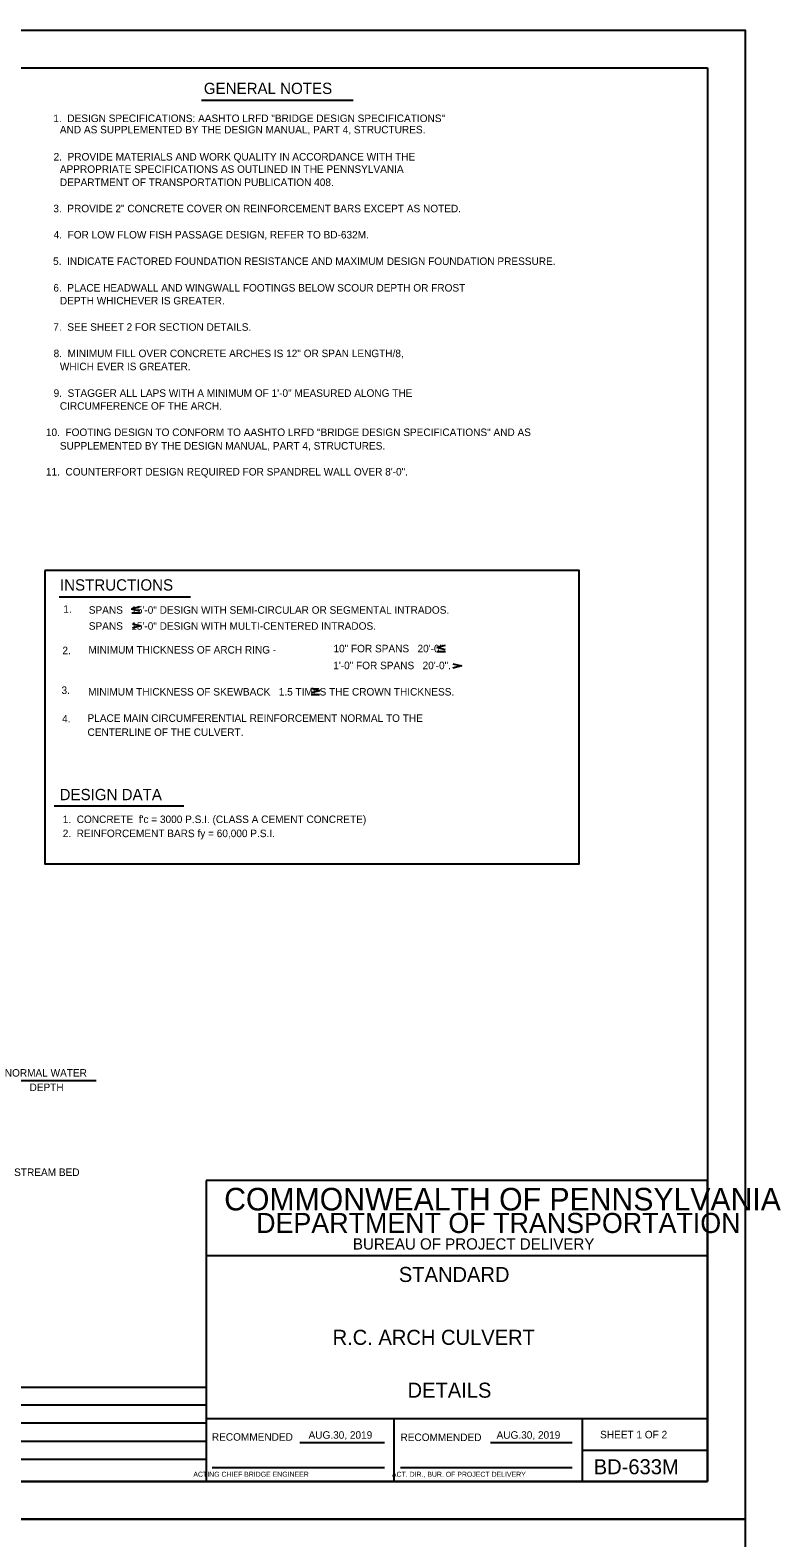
# Model space of a CAD drawing. Extents: x 639028 to 639883, y 298843 to 300031.
# Drawn here: x 639584 to 639883, y 299430 to 300031 of the extents above; entities that cross this region are included whole.
import ezdxf

# ---------------------------------------------------------------- set-up
doc = ezdxf.new("R2010")
doc.units = 0
for name, color, linetype in [('2', 7, 'Continuous'), ('53', 7, 'Continuous'), ('PLT-BNDY', 7, 'Continuous')]:
    doc.layers.add(name, color=color, linetype=linetype)

msp = doc.modelspace()

# ---------------------------------------------------------------- linework, layer by layer
at = {"layer": '2'}
for p, q in [((639067.74, 300016.08), (639853.74, 300016.08)), ((639853.74, 300016.08), (639853.74, 299452.08)), ((639627.38, 299800.99), (639624, 299800.11)), ((639627.38, 299799.24), (639624, 299800.11)), ((639627.52, 299798.42), (639624.14, 299798.42)), ((639749.17, 299785.64), (639745.8, 299784.76)), ((639749.17, 299783.89), (639745.8, 299784.76)), ((639749.31, 299783.07), (639745.94, 299783.07)), ((639695.65, 299765.98), (639699.02, 299765.98)), ((639695.78, 299768.55), (639699.16, 299767.67)), ((639695.78, 299766.8), (639699.16, 299767.67)), ((639571.61, 299612.08), (639609.99, 299612.08)), ((639853.74, 299572.08), (639653.74, 299572.08)), ((639653.74, 299572.08), (639653.74, 299452.08)), ((639853.74, 299452.08), (639853.74, 299572.08)), ((639853.74, 299542.08), (639653.74, 299542.08)), ((639446.74, 299489.7), (639653.74, 299489.7)), ((639446.74, 299482.58), (639653.74, 299482.58)), ((639653.74, 299482.58), (639653.74, 299452.08)), ((639446.74, 299475.45), (639653.74, 299475.45)), ((639853.74, 299477.08), (639653.74, 299477.08)), ((639728.74, 299452.08), (639728.74, 299477.08)), ((639803.74, 299477.08), (639803.74, 299452.08)), ((639446.74, 299468.2), (639653.74, 299468.2)), ((639691.2, 299467.58), (639724.89, 299467.58)), ((639767.18, 299467.58), (639799.79, 299467.58)), ((639803.74, 299464.58), (639853.74, 299464.58)), ((639446.74, 299460.95), (639653.74, 299460.95)), ((639656.24, 299457.58), (639724.89, 299457.58)), ((639731.36, 299457.58), (639799.79, 299457.58)), ((639853.74, 299452.08), (639067.74, 299452.08)), ((639446.74, 299452.08), (639653.74, 299452.08)), ((639653.74, 299452.08), (639853.74, 299452.08))]:
    msp.add_line(p, q, dxfattribs=at)
msp.add_lwpolyline([(639589.49, 299815.5), (639589.49, 299698.5), (639802.53, 299698.5), (639802.53, 299815.5)], close=True, dxfattribs=at)
for points in [[(639624.37, 299794.26), (639627.74, 299793.39), (639624.37, 299792.51)], [(639752.21, 299778.29), (639755.58, 299777.42), (639752.21, 299776.54)]]:
    msp.add_lwpolyline(points, dxfattribs=at)
at = {"layer": '53'}
for p, q in [((639652, 300003.17), (639712.38, 300003.17)), ((639595.24, 299805), (639647.61, 299805)), ((639593.24, 299721.66), (639644.86, 299721.66))]:
    msp.add_line(p, q, dxfattribs=at)
at = {"layer": 'PLT-BNDY'}
for points in [[(639027.74, 300031.08), (639868.74, 300031.08), (639868.74, 299437.08), (639027.74, 299437.08)], [(639027.74, 299437.08), (639868.74, 299437.08), (639868.74, 298843.08), (639027.74, 298843.08)]]:
    msp.add_lwpolyline(points, close=True, dxfattribs=at)

# ---------------------------------------------------------------- texts
at = {"layer": '2'}
for s, height, p in [('1.  DESIGN SPECIFICATIONS: AASHTO LRFD "BRIDGE DESIGN SPECIFICATIONS"', 3, (639592.86, 299994.41)), ('     AND AS SUPPLEMENTED BY THE DESIGN MANUAL, PART 4, STRUCTURES.', 3, (639589.89, 299989.9)), ('2.  PROVIDE MATERIALS AND WORK QUALITY IN ACCORDANCE WITH THE', 3, (639592.97, 299979.07)), ('     APPROPRIATE SPECIFICATIONS AS OUTLINED IN THE PENNSYLVANIA', 3, (639589.89, 299974.15)), ('     DEPARTMENT OF TRANSPORTATION PUBLICATION 408.', 3, (639589.89, 299968.9)), ('3.  PROVIDE 2" CONCRETE COVER ON REINFORCEMENT BARS EXCEPT AS NOTED.', 3, (639592.86, 299958.42)), ('4.  FOR LOW FLOW FISH PASSAGE DESIGN, REFER TO BD-632M.', 3, (639592.97, 299947.96)), ('5.  INDICATE FACTORED FOUNDATION RESISTANCE AND MAXIMUM DESIGN FOUNDATION PRESSURE.', 3, (639592.75, 299937.4)), ('6.  PLACE HEADWALL AND WINGWALL FOOTINGS BELOW SCOUR DEPTH OR FROST', 3, (639592.86, 299926.79)), ('     DEPTH WHICHEVER IS GREATER.', 3, (639589.89, 299921.65)), ('7.  SEE SHEET 2 FOR SECTION DETAILS.', 3, (639592.86, 299911.15)), ('8.  MINIMUM FILL OVER CONCRETE ARCHES IS 12" OR SPAN LENGTH/8,', 3, (639592.97, 299900.62)), ('     WHICH EVER IS GREATER.', 3, (639589.89, 299895.4)), ('9.  STAGGER ALL LAPS WITH A MINIMUM OF 1\'-0" MEASURED ALONG THE', 3, (639592.97, 299884.79)), ('     CIRCUMFERENCE OF THE ARCH.', 3, (639589.89, 299879.65)), ('10.  FOOTING DESIGN TO CONFORM TO AASHTO LRFD "BRIDGE DESIGN SPECIFICATIONS" AND AS', 3, (639589.89, 299869.15)), ('     SUPPLEMENTED BY THE DESIGN MANUAL, PART 4, STRUCTURES.', 3, (639589.89, 299863.75)), ('11.  COUNTERFORT DESIGN REQUIRED FOR SPANDREL WALL OVER 8\'-0".', 3, (639589.89, 299853.4)), ('1.', 3, (639596.86, 299798.62)), ('SPANS   15\'-0" DESIGN WITH SEMI-CIRCULAR OR SEGMENTAL INTRADOS.', 3, (639606.99, 299798.25)), ('SPANS   15\'-0" DESIGN WITH MULTI-CENTERED INTRADOS.', 3, (639606.99, 299791.87)), ('2.', 3, (639596.49, 299782.12)), ('MINIMUM THICKNESS OF ARCH RING -', 3, (639606.86, 299782.37)), ('10" FOR SPANS   20\'-0".', 3, (639704.56, 299782.87)), ('1\'-0" FOR SPANS   20\'-0".', 3, (639704.48, 299776.12)), ('3.', 3, (639596.11, 299766.25)), ('MINIMUM THICKNESS OF SKEWBACK   1.5 TIMES THE CROWN THICKNESS.', 3, (639606.74, 299765.62)), ('4.', 3, (639596.36, 299754.87)), ('PLACE MAIN CIRCUMFERENTIAL REINFORCEMENT NORMAL TO THE', 3, (639606.49, 299755.12)), ('CENTERLINE OF THE CULVERT.', 3, (639606.49, 299749.5)), ("1.  CONCRETE  f'c = 3000 P.S.I. (CLASS A CEMENT CONCRETE)", 3, (639596.61, 299714.75)), ('2.  REINFORCEMENT BARS fy = 60,000 P.S.I.', 3, (639596.61, 299709.12)), ('NORMAL WATER', 3, (639573.49, 299613.58)), ('DEPTH', 3, (639583.36, 299607.83)), ('STREAM BED', 3, (639577.24, 299573.95)), ('COMMONWEALTH OF PENNSYLVANIA', 9, (639660.99, 299560.2)), ('DEPARTMENT OF TRANSPORTATION', 8.0002, (639673.74, 299551.2)), ('BUREAU OF PROJECT DELIVERY', 4.5, (639712.33, 299544.58)), ('STANDARD', 6, (639730.64, 299531.66)), ('R.C. ARCH CULVERT', 6, (639704.22, 299506.58)), ('DETAILS', 6, (639734.11, 299485.49)), ('AUG.30, 2019', 3, (639694.62, 299469.12)), ('AUG.30, 2019', 3, (639769.62, 299469.12)), ('SHEET 1 OF 2', 3, (639810.89, 299469.28)), ('BD-633M', 6, (639808.36, 299454.95)), ('       ACTING CHIEF BRIDGE ENGINEER', 2.0002, (639643.33, 299453.95)), ('   ACT. DIR., BUR. OF PROJECT DELIVERY', 2.0002, (639725.57, 299453.94))]:
    msp.add_text(s, height=height, dxfattribs=at).set_placement(p)
for p in [(639656.08, 299468.33), (639731.29, 299468.2)]:
    msp.add_text('RECOMMENDED', height=3, rotation=360, dxfattribs=at).set_placement(p)
at = {"layer": '53'}
for s, p in [('GENERAL NOTES', (639652.88, 300005.6)), ('INSTRUCTIONS', (639595.49, 299807.5)), ('DESIGN DATA', (639595.36, 299723.87))]:
    msp.add_text(s, height=4.5, dxfattribs=at).set_placement(p)

doc.saveas('drawing.dxf')
